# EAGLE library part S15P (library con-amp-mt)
AMP MT CONNECTOR
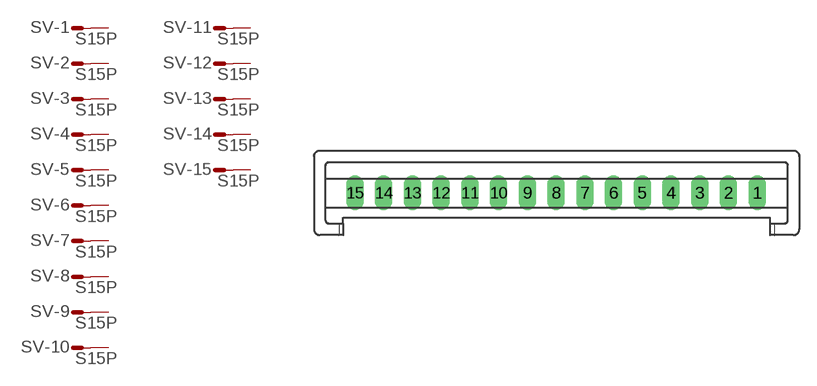
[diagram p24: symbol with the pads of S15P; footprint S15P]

Designator prefix SV; gates -1=M -2=M -3=M -4=M -5=M -6=M -7=M -8=M -9=M -10=M -11=M -12=M -13=M -14=M -15=M

## S15P (OC_FARNELL: unknown; OC_NEWARK: unknown)  [S15P]
1  -1:S  pas
2  -2:S  pas
3  -3:S  pas
4  -4:S  pas
5  -5:S  pas
6  -6:S  pas
7  -7:S  pas
8  -8:S  pas
9  -9:S  pas
10  -10:S  pas
11  -11:S  pas
12  -12:S  pas
13  -13:S  pas
14  -14:S  pas
15  -15:S  pas

## Footprint S15P (pad centres in mm)
AMP MT CONNECTOR
drill 1.016 long: 1 17.5,0; 2 15,0; 3 12.5,0; 4 10,0; 5 7.5,0; 6 5,0; 7 2.5,0; 8 0,0; 9 -2.5,0; 10 -5,0; 11 -7.5,0; 12 -10,0; 13 -12.5,0; 14 -15,0; 15 -17.5,0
